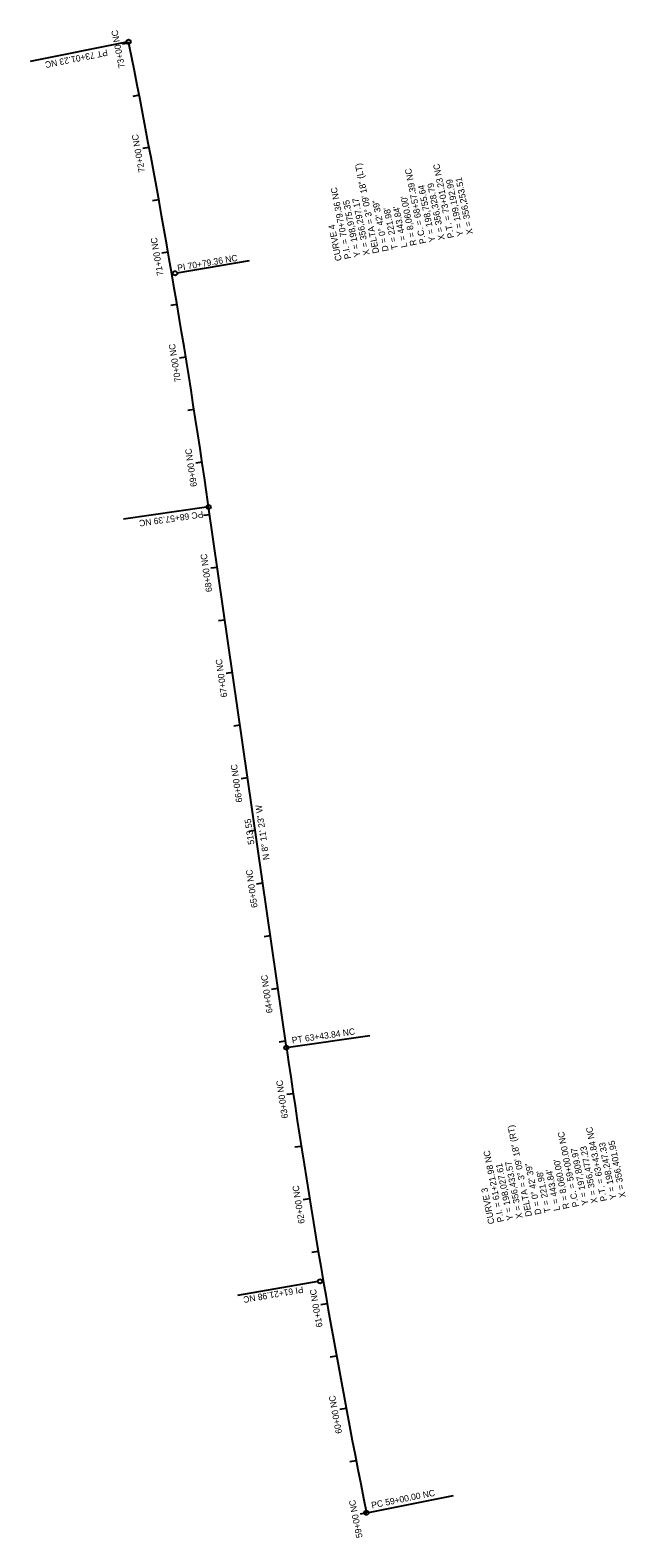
# Model space of a CAD drawing. Extents: x 356161 to 360393, y 172819 to 199204.
# Drawn here: x 356161 to 356721, y 197786 to 199204 of the extents above; entities that cross this region are included whole.
import ezdxf

# ---------------------------------------------------------------- set-up
doc = ezdxf.new("R2010")
doc.units = 0
for name, color, linetype in [('CA-MTCH-LINE', 7, 'Continuous'), ('CA-MTCH-LINE-TEXT', 7, 'Continuous'), ('Default', 7, 'Continuous'), ('Level 28', 7, 'Continuous'), ('P_PM_DotLane_50', 7, 'Continuous'), ('P_TC_Text', 7, 'Continuous')]:
    doc.layers.add(name, color=color, linetype=linetype)

msp = doc.modelspace()

# ---------------------------------------------------------------- linework, layer by layer
at = {"layer": 'CA-MTCH-LINE-TEXT'}
for p, q in [((356253.7, 199191.8), (356247.9, 199190.6)), ((356263.4, 199142.7), (356257.5, 199141.6)), ((356272.8, 199093.6), (356266.9, 199092.5)), ((356281.9, 199044.4), (356276, 199043.4)), ((356290.6, 198995.2), (356284.7, 198994.2)), ((356299.1, 198945.9), (356293.2, 198944.9)), ((356307.2, 198896.6), (356301.3, 198895.6)), ((356315.1, 198847.2), (356309.1, 198846.3)), ((356322.6, 198797.8), (356316.7, 198796.9)), ((356329.8, 198748.3), (356323.9, 198747.5)), ((356337, 198698.8), (356331, 198698)), ((356344.1, 198649.3), (356338.2, 198648.5)), ((356351.2, 198599.9), (356345.3, 198599)), ((356358.3, 198550.4), (356352.4, 198549.5)), ((356365.5, 198500.9), (356359.5, 198500)), ((356372.6, 198451.4), (356366.6, 198450.5)), ((356379.7, 198401.9), (356373.8, 198401)), ((356386.8, 198352.4), (356380.9, 198351.5)), ((356393.9, 198302.9), (356388, 198302.1)), ((356401.1, 198253.4), (356395.1, 198252.6)), ((356408.3, 198204), (356402.4, 198203.1)), ((356415.9, 198154.5), (356409.9, 198153.6)), ((356423.7, 198105.1), (356417.8, 198104.2)), ((356431.9, 198055.8), (356425.9, 198054.8)), ((356440.3, 198006.5), (356434.4, 198005.5)), ((356449.1, 197957.3), (356443.2, 197956.2)), ((356458.2, 197908.1), (356452.3, 197907)), ((356467.6, 197859), (356461.7, 197857.9)), ((356477.2, 197810), (356471.4, 197808.8))]:
    msp.add_line(p, q, dxfattribs=at)
at = {"layer": 'Level 28'}
for p, q in [((356251.5, 199192.6), (356160.9, 199174.4)), ((356299.1, 198975.7), (356367.2, 198987.4)), ((356326.8, 198755.4), (356248.7, 198744.1)), ((356403.9, 198247.6), (356480.4, 198258.6)), ((356431.6, 198027.3), (356356, 198014.3)), ((356479.2, 197810.4), (356559.2, 197826.4))]:
    msp.add_line(p, q, dxfattribs=at)
for centre in [(356253.5, 199193), (356297.2, 198975.3), (356328.8, 198755.6), (356401.9, 198247.3), (356433.6, 198027.6), (356477.2, 197810)]:
    msp.add_circle(centre, 2, dxfattribs=at)
at = {"layer": 'P_PM_DotLane_50'}
msp.add_line((356401.9, 198247.3), (356328.8, 198755.6), dxfattribs=at)
for centre, start, end in [((348351, 197607.5), 8.18965, 11.34476), ((364379.8, 199395.5), 188.18965, 191.34476)]:
    msp.add_arc(centre, 8060, start, end, dxfattribs=at)

# ---------------------------------------------------------------- texts
at = {"layer": 'CA-MTCH-LINE'}
for s, rotation, p in [('73+00 NC', 101.336, (356250.2, 199168.8)), ('72+00 NC', 100.6252, (356269, 199070.7)), ('71+00 NC', 99.9143, (356286.3, 198973.6)), ('70+00 NC', 99.2034, (356302.9, 198873.6)), ('69+00 NC', 98.4926, (356317.9, 198775)), ('68+00 NC', 98.1897, (356332.2, 198676.1)), ('67+00 NC', 98.1897, (356346.4, 198577.1)), ('66+00 NC', 98.1897, (356360.6, 198478.2)), ('65+00 NC', 98.1897, (356374.9, 198379.2)), ('64+00 NC', 98.1897, (356389.1, 198280.2)), ('63+00 NC', 98.5013, (356403.6, 198181.2)), ('62+00 NC', 99.2122, (356419.3, 198082.3)), ('61+00 NC', 99.923, (356436, 197984.9)), ('60+00 NC', 100.6339, (356454.4, 197885)), ('59+00 NC', 101.3448, (356473.7, 197787))]:
    msp.add_text(s, height=6, rotation=rotation, dxfattribs=at).set_placement(p)
at = {"layer": 'Default'}
for s, p in [('N 8%%d 11\' 23" W', (356386.1, 198424.2)), ('513.55', (356371.9, 198438.6))]:
    msp.add_text(s, height=6, rotation=98.1897, dxfattribs=at).set_placement(p)
at = {"layer": 'Level 28'}
for s, rotation, p in [('PT 73+01.23 NC', 191.3448, (356233.2, 199185.9)), ('PI 70+79.36 NC', 9.7672, (356299.9, 198977.3)), ('PC 68+57.39 NC', 188.1897, (356323.3, 198751.8)), ('PT 63+43.84 NC', 8.1897, (356407.5, 198251.2)), ('PI 61+21.98 NC', 189.7672, (356417.4, 198022.9)), ('PC 59+00.00 NC', 11.3448, (356482.5, 197814.1))]:
    msp.add_text(s, height=6, rotation=rotation, dxfattribs=at).set_placement(p)
at = {"layer": 'P_TC_Text'}
for s, p in [('DELTA = 3%%d 09\' 18" (LT)', (356489.3, 198994.6)), ('P.C. = 68+57.39 NC', (356533.5, 199003.6)), ('P.T. = 73+01.23 NC', (356559.9, 199008.9)), ('X = 356,253.51', (356577.6, 199012.5)), ('P.I. = 70+79.36 NC', (356462.9, 198989.3)), ('Y = 198,755.64', (356542.3, 199005.3)), ('X = 356,328.79', (356551.1, 199007.1)), ('Y = 199,192.99', (356568.7, 199010.7)), ('Y = 198,975.35', (356471.7, 198991.1)), ('X = 356,297.17', (356480.5, 198992.9)), ('D = 0%%d 42\' 39"', (356498.2, 198996.4)), ("T = 221.98'", (356507, 198998.2)), ("L = 443.84'", (356515.8, 199000)), ("R = 8,060.00'", (356524.6, 199001.8)), ('CURVE 4', (356454.1, 198987.5)), ('DELTA = 3%%d 09\' 18" (RT)', (356633.1, 198089.1)), ('P.T. = 63+43.84 NC', (356703.7, 198103.4)), ('P.C. = 59+00.00 NC', (356677.3, 198098)), ('Y = 198,247.33', (356712.5, 198105.1)), ('X = 356,401.95', (356721.4, 198106.9)), ('P.I. = 61+21.98 NC', (356606.7, 198083.8)), ('Y = 197,809.97', (356686.1, 198099.8)), ('X = 356,477.23', (356694.9, 198101.6)), ('Y = 198,027.61', (356615.5, 198085.5)), ('X = 356,433.57', (356624.3, 198087.3)), ('D = 0%%d 42\' 39"', (356642, 198090.9)), ("T = 221.98'", (356650.8, 198092.7)), ("L = 443.84'", (356659.6, 198094.5)), ("R = 8,060.00'", (356668.4, 198096.2)), ('CURVE 3', (356597.9, 198082))]:
    msp.add_text(s, height=6, rotation=101.4103, dxfattribs=at).set_placement(p)

doc.saveas('drawing.dxf')
